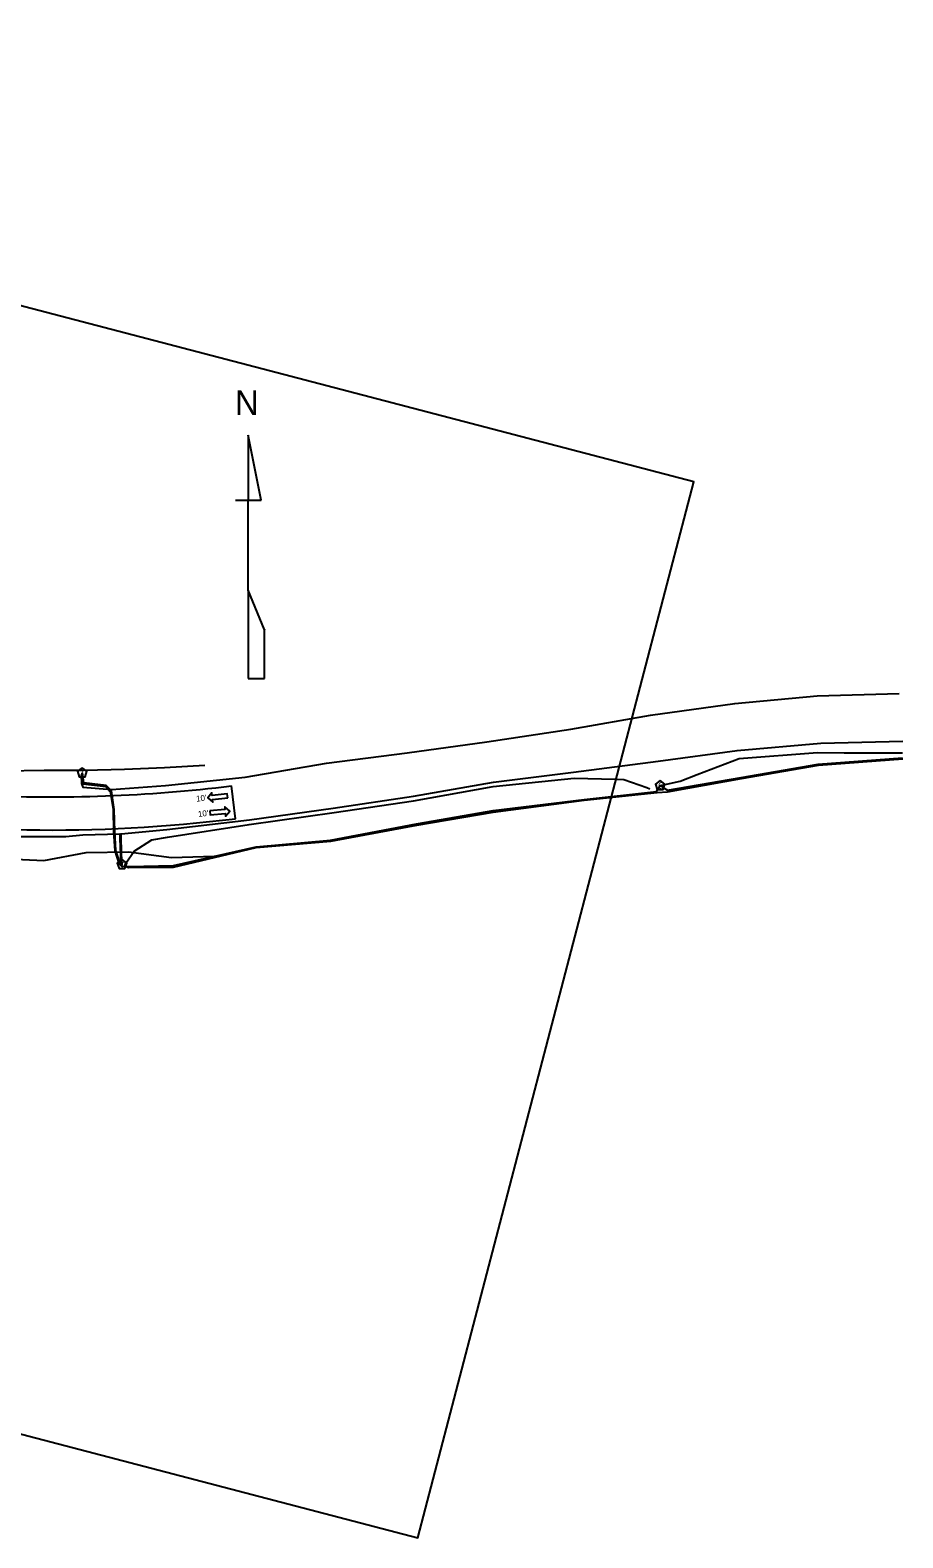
# Model space of a CAD drawing. Extents: x 1749937 to 1751313, y 1197512 to 1198424.
# Drawn here: x 1750785 to 1751313, y 1197512 to 1198424 of the extents above; entities that cross this region are included whole.
import ezdxf

# ---------------------------------------------------------------- set-up
doc = ezdxf.new("R2010")
doc.units = 0
for name, color, linetype in [('RD_EX_Misc', 7, 'Continuous'), ('RD_EX_SU_Telecom', 7, 'Continuous'), ('RD_PD_CstnLmt', 7, 'Continuous'), ('RD_PD_Final_TrvlWay', 7, 'Continuous'), ('RD_PD_Final_TX', 7, 'Continuous'), ('RD_SHT_TX', 7, 'Continuous'), ('RD_Sketch8', 7, 'Continuous')]:
    doc.layers.add(name, color=color, linetype=linetype)

msp = doc.modelspace()

# ---------------------------------------------------------------- linework, layer by layer
at = {"layer": 'RD_EX_Misc'}
for p, q in [((1750925.03, 1198140.02), (1750917.19, 1198179.22)), ((1750917.19, 1198179.22), (1750917.19, 1198179.22)), ((1750917.19, 1198179.22), (1750917.19, 1198140.02)), ((1750909.35, 1198140.02), (1750917.19, 1198140.02)), ((1750917.19, 1198085.62), (1750917.19, 1198140.02)), ((1750917.19, 1198140.02), (1750925.03, 1198140.02)), ((1750925.03, 1198140.02), (1750925.03, 1198140.49)), ((1750926.99, 1198061.62), (1750917.19, 1198085.62)), ((1750917.19, 1198085.62), (1750917.19, 1198032.22)), ((1750926.99, 1198032.22), (1750926.99, 1198061.89)), ((1750926.99, 1198061.89), (1750926.99, 1198061.62)), ((1750917.19, 1198032.22), (1750926.99, 1198032.22))]:
    msp.add_line(p, q, dxfattribs=at)
at = {"layer": 'RD_EX_SU_Telecom'}
for points in [[(1750816.63, 1197975.17), (1750816.1, 1197973.55), (1750816.26, 1197968.67), (1750817.1, 1197966.47), (1750834.34, 1197964.95), (1750867.15, 1197967.44), (1750915.18, 1197972.42), (1750964.44, 1197980.86), (1751013.36, 1197987.14), (1751061.43, 1197993.91), (1751112.25, 1198001.62), (1751160.48, 1198010.06), (1751211.6, 1198017.02), (1751261.33, 1198021.65), (1751310.97, 1198023.07)], [(1750840.8, 1197919.61), (1750840.59, 1197920.98), (1750840.24, 1197935.13), (1750840.16, 1197938.24), (1750867.93, 1197940.89), (1750917.81, 1197946.73), (1750968.52, 1197953.68), (1751017.11, 1197960.92), (1751065.43, 1197969.39), (1751113.94, 1197975.58), (1751165.05, 1197982.22), (1751212.83, 1197988.54), (1751263.62, 1197993.11), (1751313.16, 1197994.27)], [(1750842.43, 1197918.73), (1750844.94, 1197918.39), (1750871.84, 1197919.06), (1750921.87, 1197930.45), (1750966.9, 1197934.41), (1751018.98, 1197944.36), (1751065.21, 1197952.3), (1751120.27, 1197959.07), (1751164.07, 1197963.76), (1751165.35, 1197966.12), (1751166.3, 1197967.39), (1751167.84, 1197966.45), (1751170.82, 1197964.55), (1751215.36, 1197972.36), (1751262, 1197980.28), (1751313.04, 1197984.13)], [(1750842.43, 1197918.73), (1750844.77, 1197917.84), (1750871.87, 1197918.15), (1750921.93, 1197929.92), (1750967.07, 1197933.81), (1751019.05, 1197943.51), (1751065.4, 1197951.4), (1751120.45, 1197958.55), (1751164.55, 1197963.2), (1751170.72, 1197963.71), (1751215.61, 1197971.65), (1751262.08, 1197979.69), (1751313.13, 1197983.48)], [(1751166.3, 1197967.39), (1751168.28, 1197967.92), (1751178.44, 1197969.98), (1751188.65, 1197974.05), (1751214.06, 1197983.85), (1751261.61, 1197987.39), (1751277.58, 1197987.15), (1751312.87, 1197987.25)], [(1750766.73, 1197936.52), (1750806.88, 1197936.68), (1750817.12, 1197937.72), (1750839.37, 1197938.23), (1750839.38, 1197935.32), (1750840.12, 1197920.77), (1750840.8, 1197919.61), (1750839.63, 1197920.5), (1750836.94, 1197928.22), (1750836.37, 1197939.68), (1750835.96, 1197952.91), (1750834.4, 1197964.29), (1750831.12, 1197967.55), (1750817.59, 1197969.07), (1750817.15, 1197973.81), (1750816.63, 1197975.17)], [(1750816.63, 1197975.17), (1750816.44, 1197973.52), (1750817.1, 1197968.4), (1750830.92, 1197966.92), (1750833.64, 1197963.83), (1750835.46, 1197952.99), (1750835.68, 1197939.58), (1750836.38, 1197927.93), (1750838.84, 1197920.26), (1750840.74, 1197918.53), (1750842.43, 1197918.73)], [(1750842.43, 1197918.73), (1750843.07, 1197920.49), (1750848.19, 1197927.84), (1750858.8, 1197934.64), (1750868.39, 1197936.28), (1750917.74, 1197943.9), (1750969.06, 1197951.16), (1751017.2, 1197958.13), (1751065.26, 1197966.92), (1751114.25, 1197971.96), (1751139.13, 1197971.24), (1751144.43, 1197971.13), (1751158.27, 1197966.34), (1751160.03, 1197965.47)]]:
    msp.add_lwpolyline(points, dxfattribs=at)
for points in [[(1750816.63, 1197978.17), (1750813.78, 1197976.1), (1750814.87, 1197972.75), (1750818.39, 1197972.75), (1750819.48, 1197976.1)], [(1751166.3, 1197970.39), (1751163.44, 1197968.32), (1751164.53, 1197964.96), (1751168.06, 1197964.96), (1751169.15, 1197968.32)], [(1750840.8, 1197922.61), (1750837.94, 1197920.54), (1750839.03, 1197917.18), (1750842.56, 1197917.18), (1750843.65, 1197920.54)]]:
    msp.add_lwpolyline(points, close=True, dxfattribs=at)
at = {"layer": 'RD_PD_CstnLmt'}
for p, q in [((1750769.33, 1197976.37), (1750793.64, 1197976.67)), ((1750793.64, 1197976.67), (1750817.94, 1197976.75)), ((1750817.94, 1197976.75), (1750842.24, 1197977.3)), ((1750842.24, 1197977.3), (1750866.54, 1197978.28)), ((1750866.54, 1197978.28), (1750890.84, 1197979.75)), ((1750767.72, 1197923.21), (1750793.47, 1197922.06)), ((1750793.47, 1197922.06), (1750819.13, 1197926.87)), ((1750819.13, 1197926.87), (1750844.78, 1197927.35)), ((1750844.78, 1197927.35), (1750870.78, 1197923.98)), ((1750870.78, 1197923.98), (1750896.62, 1197924.81))]:
    msp.add_line(p, q, dxfattribs=at)
at = {"layer": 'RD_PD_Final_TrvlWay'}
msp.add_line((1750909.47, 1197947.37), (1750907.05, 1197967.22), dxfattribs=at)
for radius, start in [(935, 245.97379), (915, 267.35356)]:
    msp.add_arc((1750796.56, 1198875.53), radius, start, 276.93571, dxfattribs=at)
at = {"layer": 'RD_PD_Final_TX'}
for points in [[(1750904.71, 1197959.96), (1750904.47, 1197962.35), (1750895.34, 1197961.4), (1750895.18, 1197963.02), (1750892.65, 1197959.91), (1750895.76, 1197957.39), (1750895.59, 1197959.01)], [(1750893.93, 1197952.11), (1750894.14, 1197949.72), (1750903.27, 1197950.49), (1750903.41, 1197948.87), (1750905.99, 1197951.92), (1750902.94, 1197954.5), (1750903.07, 1197952.88)]]:
    msp.add_lwpolyline(points, close=True, dxfattribs=at)
at = {"layer": 'RD_Sketch8'}
msp.add_lwpolyline([(1749974.91, 1197785.71), (1751019.78, 1197512.48), (1751186.75, 1198151.01), (1750141.89, 1198424.24)], close=True, dxfattribs=at)

# ---------------------------------------------------------------- texts
at = {"layer": 'RD_EX_Misc'}
msp.add_text('N', height=15, dxfattribs=at).set_placement((1750909.05, 1198191.44))
at = {"layer": 'RD_EX_SU_Telecom'}
for s, height, p in [('T', 3.75, (1750815.4, 1197972.95)), ('C', 4, (1751165.07, 1197965.39)), ('T', 3.75, (1750839.57, 1197917.38))]:
    msp.add_text(s, height=height, dxfattribs=at).set_placement(p)
at = {"layer": 'RD_SHT_TX'}
for p in [(1750885.83, 1197957.61), (1750886.95, 1197948.36)]:
    msp.add_text("10'", height=3.6, rotation=6.79668, dxfattribs=at).set_placement(p)

doc.saveas('drawing.dxf')
